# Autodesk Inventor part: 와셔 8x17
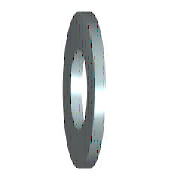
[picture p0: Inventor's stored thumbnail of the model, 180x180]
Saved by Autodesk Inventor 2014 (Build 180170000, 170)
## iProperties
IsCustomPart: 1
Created: 2012-02
Part Number: 와셔 8x17
Material: 강철, 연강
Description: 평면 와셔
Document SubType Name: Modeling
Standard: KS B 1326
Designer: mduedu
Standards Organization: KS
Language: ko-KR
Size Designation: 8x17
Categories: <MemberInstance><Categories><Category DisplayName="조임쇠" InternalName="e4da775c-781d-43d5-af7c-5136215cf5a6" Mnemonic="FSTN"><Category DisplayName="와셔" InternalN
Density: 1 g/cm^3
Appearance: Yellow
Author: mduedu
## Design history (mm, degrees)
sketch "스케치"
  geometry: C1 r 8.5 at (0, 0); C2 r 4.2 at (0, 0); 1 further point
  constraints: 2 centre point, 2 coincident
  dimensions: "d0" = 8.4 diameter of C2 (= SD1); "d1" = 17 diameter of C1 (= SD2)
extrude "본체" new body sketch "스케치" distance "d2" = 1.6 (= SD); taper "d3" = 0 deg
workaxis "Work Axis1"
workplane "Work Plane1"
body "Solid1"
other parameters: "SD1" = 8.4 [user parameter; used in 1 equation term], "SD2" = 17 [user parameter; used in 1 equation term], "SD" = 1.6 [user parameter; used in 1 equation term], "d4" = 0, "d5" = 0, "d6" = 0, "d7" = 0, "NND" = 8 [user parameter]
